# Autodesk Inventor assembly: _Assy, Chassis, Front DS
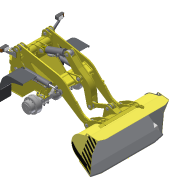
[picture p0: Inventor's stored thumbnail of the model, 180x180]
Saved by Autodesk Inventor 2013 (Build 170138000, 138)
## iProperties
Created: 2005-04
Part Number: _Assy, Chassis, Front DS
Document SubType Name: Assembly
Designer: salex
Manufacturer: Standard
Standards Organization: Custom
Author: salex
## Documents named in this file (35)
- C:\Product Design Suite 2013 Test Drive\Dynamic Simulation\Workspace\_Assy, Chassis, Front DS.iam
- C:\Product Design Suite 2013 Test Drive\Dynamic Simulation\Workspace\Assy, Chassis, Front\PK46.43.00.005.ipt
- C:\Product Design Suite 2013 Test Drive\Dynamic Simulation\Workspace\Assy, Chassis, Front\PK46.25.02.010.iam
- C:\Product Design Suite 2013 Test Drive\Dynamic Simulation\Workspace\Assy, Chassis, Front\PK46.16.10.000.iam
- C:\Product Design Suite 2013 Test Drive\Dynamic Simulation\Workspace\Assy, Chassis, Front\PK46.25.03.000.iam
- C:\Product Design Suite 2013 Test Drive\Dynamic Simulation\Workspace\Assy, Chassis, Front\PK46.43.01.010.iam
- C:\Product Design Suite 2013 Test Drive\Dynamic Simulation\Workspace\Assy, Chassis, Front\PK46.04.00.002.ipt
- C:\Product Design Suite 2013 Test Drive\Dynamic Simulation\Workspace\Assy, Chassis, Front\PK46.43.02.010.iam
- C:\Product Design Suite 2013 Test Drive\Dynamic Simulation\Workspace\Assy, Chassis, Front\PK46.04.00.030.iam
- C:\Product Design Suite 2013 Test Drive\Dynamic Simulation\Workspace\Assy, Chassis, Front\027.13.14.227.ipt
- C:\Product Design Suite 2013 Test Drive\Dynamic Simulation\Workspace\Assy, Chassis, Front\027.13.12.227.ipt
- C:\Product Design Suite 2013 Test Drive\Dynamic Simulation\Workspace\Assy, Chassis, Front\PK46.53.20.000.iam
- C:\Product Design Suite 2013 Test Drive\Dynamic Simulation\Workspace\Assy, Chassis, Front\PK46.25.00.010.iam
- C:\Product Design Suite 2013 Test Drive\Dynamic Simulation\Workspace\Assy, Chassis, Front\PK46.25.00.005.ipt
- C:\Product Design Suite 2013 Test Drive\Dynamic Simulation\Workspace\Assy, Chassis, Front\PK46.25.00.008.ipt
- C:\Product Design Suite 2013 Test Drive\Dynamic Simulation\Workspace\Assy, Chassis, Front\PK46.25.00.007.ipt
- C:\Product Design Suite 2013 Test Drive\Dynamic Simulation\Workspace\Assy, Chassis, Front\PK46.25.00.030.iam
- C:\Product Design Suite 2013 Test Drive\Dynamic Simulation\Workspace\Assy, Chassis, Front\PK46.25.00.020.iam
- C:\Product Design Suite 2013 Test Drive\Dynamic Simulation\Workspace\Assy, Chassis, Front\PK46.25.00.006.ipt
- C:\Product Design Suite 2013 Test Drive\Dynamic Simulation\Workspace\Assy, Chassis, Front\PK46.41.00.200-01.iam
- C:\Product Design Suite 2013 Test Drive\Dynamic Simulation\Workspace\Assy, Chassis, Front\PK46.20.10.000.iam
- C:\Product Design Suite 2013 Test Drive\Dynamic Simulation\Workspace\Assy, Chassis, Front\PK46.04.00.031.iam
- C:\Product Design Suite 2013 Test Drive\Dynamic Simulation\Workspace\Assy, Chassis, Front\027.13.15.227.ipt
- C:\Product Design Suite 2013 Test Drive\Dynamic Simulation\Workspace\Assy, Chassis, Front\027.13.16.227.ipt
- C:\Product Design Suite 2013 Test Drive\Dynamic Simulation\Workspace\Assy, Chassis, Front\PK46.43.04.020.iam
- C:\Product Design Suite 2013 Test Drive\Dynamic Simulation\Workspace\Assy, Chassis, Front\PK46.43.03.020.iam
- C:\Product Design Suite 2013 Test Drive\Dynamic Simulation\Workspace\Assy, Chassis, Front\PK46.41.00.200-02.iam
- C:\Product Design Suite 2013 Test Drive\Dynamic Simulation\Workspace\Assy, Chassis, Front\PK46.53.20.001.iam
- C:\Product Design Suite 2013 Test Drive\Dynamic Simulation\Workspace\Assy, Chassis, Front\PK46.21.01.100.iam
- C:\Product Design Suite 2013 Test Drive\Dynamic Simulation\Workspace\Assy, Chassis, Front\PK46.80.00.000.iam
- C:\Product Design Suite 2013 Test Drive\Dynamic Simulation\Workspace\Assy, Chassis, Front\PK46.21.01.200.iam
- C:\Product Design Suite 2013 Test Drive\Dynamic Simulation\Workspace\Assy, Chassis, Front\PK46.21.01.090.ipt
- C:\Product Design Suite 2013 Test Drive\Dynamic Simulation\Workspace\Assy, Chassis, Front\PK46.21.01.091.ipt
- C:\Product Design Suite 2013 Test Drive\Dynamic Simulation\Workspace\Assy, Chassis, Front\PK46.21.01.092.ipt
- C:\Product Design Suite 2013 Test Drive\Dynamic Simulation\Workspace\Assy, Chassis, Front\PK46.25.01.000.iam
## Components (125 placed, 34 different names)
1. PK46.21.01.100:1 [sub-assembly] — Вставка:1, Совмещение:1, Совмещение:3, Угол:1, Совмещение:4, Вставка:6, Вставка:9, Угол:2, Вставка:10, Вставка:20, Вставка:21, Вставка:22, Вставка:23, Угол:11, Угол:12, Угол:13, Угол:14, Mate:20, Угол:19, Mate:21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
2. PK46.80.00.000:1 [sub-assembly] — Mate Bucket yoke, tangent boom down, Заподлицо:7, Заподлицо:9, Вставка:35, Вставка:36, Вставка:45, Вставка:46, Вставка:48, Вставка:49, Mate:88, Mate:107, Mate:108
3. PK46.21.01.200:1 [sub-assembly] — Вставка:1, Совмещение:1, Вставка:12, Вставка:13, Вставка:14, Вставка:15, Угол:3, Угол:4, Угол:5, Угол:6, Совмещение:18, Insert:99, Insert:100, Insert:101, Insert:102
4. PK46.25.02.010:1 [sub-assembly] — Совмещение:6, Совмещение:7, Совмещение:11, Вставка:27, Совмещение:48, Вставка:28, Вставка:29, Вставка:40, Вставка:41, Совмещение:49, Mate:94, Mate:95, Mate:96, Mate:105, Mate:106, Mate:109
5. PK46.25.03.000:1 [sub-assembly] — Совмещение:6, Совмещение:7, Mate Bucket yoke, Mate:88, Mate:108, Mate:109
6. PK46.16.10.000:1 [sub-assembly] — Совмещение:3, Угол:1, Совмещение:4, Insert:111, Insert:112, Insert:113, Insert:114, Insert:116, Insert:121, Insert:122, Insert:123
7. PK46.43.03.020:1 [sub-assembly] — Совмещение:9, Вставка:6, Угол:21, Mate:100
8. PK46.43.01.010:1 [sub-assembly] — Совмещение:47, Вставка:76, Вставка:77, Вставка:79
9. PK46.43.01.010:2 [sub-assembly] — Совмещение:9, Угол:21, Вставка:81, Вставка:82, Mate:100
10. PK46.04.00.002:1 — Вставка:9, Угол:2
11. PK46.43.04.020:1 [sub-assembly] — Вставка:10, Совмещение:12, Angle:25, _Mate:101 extension cyl middle
12. PK46.43.02.010:1 [sub-assembly] — Совмещение:11, Совмещение:12, Angle:25, _Mate:101 extension cyl middle, Mate:105, Flush:23
13. PK46.53.20.000:1 [sub-assembly] — Mate:20, Угол:19, Mate:21, Flush:16
14. PK46.53.20.001:1 [sub-assembly]
15. PK46.21.01.090:1 — Совмещение:23, Заподлицо:4, Совмещение:24, Совмещение:25, Совмещение:27
16. PK46.21.01.090:2 — Совмещение:25, Совмещение:26, Совмещение:27
17. PK46.21.01.091:1 — Заподлицо:7, Заподлицо:9
18. PK46.43.00.005:1 — Вставка:25, Совмещение:41, Вставка:26
19. PK46.43.00.005:2 — Вставка:25, Совмещение:41, Совмещение:42, Flush:20, Flush:21
20. PK46.21.01.092:1 — Совмещение:44, Совмещение:45, Совмещение:46
21. PK46.43.03.020:2 [sub-assembly] — Совмещение:47, Совмещение:83, Mate:89, Flush:17
22. PK46.25.00.010:1 [sub-assembly] — Вставка:27, Совмещение:48
23. PK46.25.00.005:1 — Вставка:28
24. PK46.25.00.005:2 — Вставка:29, Вставка:30
25. PK46.25.00.008:1 — Вставка:30, Вставка:31, Flush:23
26. PK46.25.00.007:1 — Вставка:31
27. PK46.25.00.030:1 [sub-assembly] — Flush:12, Mate:96, Mate:97, Mate:98
28. PK46.25.00.008:2 — Вставка:34, Mate:98
29. PK46.25.00.005:4 — Вставка:36, Вставка:38
30. PK46.25.00.007:2 — Вставка:34, Mate:97
31. PK46.25.00.010:2 [sub-assembly] — Вставка:37
32. PK46.25.00.008:3 — Вставка:38, Вставка:39
33. PK46.25.00.007:3 — Вставка:39
34. PK46.25.00.005:7 — Вставка:41, Вставка:43
35. PK46.25.00.005:8 — Вставка:40, Вставка:42
36. PK46.25.00.010:3 [sub-assembly] — Вставка:42, Совмещение:49
37. PK46.25.00.007:4 — Вставка:44
38. PK46.25.00.008:4 — Вставка:43, Вставка:44
39. PK46.25.00.020:1 [sub-assembly] — Вставка:45, Mate:99
40. PK46.25.00.008:5 — Вставка:46, Вставка:47
41. PK46.25.00.007:5 — Вставка:47
42. PK46.25.00.007:6 — Вставка:50
43. PK46.25.00.020:2 [sub-assembly] — Вставка:48
44. PK46.25.00.005:5 — Вставка:35, Вставка:37
45. PK46.25.00.008:6 — Вставка:49, Вставка:50
46. PK46.25.00.020:3 [sub-assembly] — Вставка:60, Mate:102, Mate:104
47. PK46.25.00.020:4 [sub-assembly] — Вставка:53, Совмещение:83, Mate:89, Mate:102, Mate:103, Mate:104
48. PK46.25.00.006:1 — Вставка:53
49. PK46.25.00.006:2 — Вставка:52, Вставка:54
50. PK46.25.00.008:7 — Вставка:54, Вставка:55
51. PK46.25.00.007:7 — Вставка:55
52. PK46.25.00.006:3 — Insert:56, Вставка:60
53. PK46.25.00.006:4 — Вставка:57
54. PK46.25.00.008:8 — Вставка:58, Вставка:59
55. PK46.25.00.007:8 — Вставка:59
56. PK46.25.00.020:5 [sub-assembly] — Вставка:69
57. PK46.25.00.006:5 — Insert:61, Вставка:70
58. PK46.25.00.006:6 — Вставка:69
59. PK46.25.00.008:9 — Вставка:65, Вставка:68
60. PK46.25.00.007:9 — Вставка:68
61. PK46.25.00.020:6 [sub-assembly] — Вставка:70, Mate:90
62. PK46.25.00.006:7 — Вставка:63, Вставка:65
63. PK46.25.00.006:8 — Вставка:62, Вставка:66
64. PK46.25.00.008:10 — Вставка:66, Вставка:67
65. PK46.25.00.007:10 — Вставка:67
66. PK46.25.00.010:4 [sub-assembly] — Вставка:73
67. PK46.25.00.005:9 — Вставка:71
68. PK46.25.00.005:10 — Вставка:72
69. PK46.25.00.008:11 — Вставка:74, Вставка:75
70. PK46.25.00.007:11 — Вставка:75
71. PK46.25.00.005:11 — Вставка:77
72. PK46.25.00.005:12 — Вставка:76, Вставка:78
73. PK46.25.00.010:5 [sub-assembly] — Вставка:78, _ Mate:93 Left Fore Cyl, Mate:111
74. PK46.25.00.007:12 — Вставка:80
75. PK46.25.00.008:12 — Вставка:79, Вставка:80
76. PK46.25.00.005:13 — Вставка:82, Вставка:83
77. PK46.25.00.005:14 — Вставка:81, Вставка:84
78. PK46.25.00.010:6 [sub-assembly] — Вставка:83, _ Mate:92 Right Fore Cyl, Mate:110
79. PK46.25.00.007:14 — Вставка:85
80. PK46.25.00.008:14 — Вставка:84, Вставка:85
81. PK46.41.00.200-01:1 [sub-assembly] — Flush:15, Flush:16, Flush:18
82. PK46.41.00.200-02:1 [sub-assembly]
83. PK46.25.01.000:1 [sub-assembly] — Mate:90, Mate:91, _ Mate:92 Right Fore Cyl, _ Mate:93 Left Fore Cyl, Mate:94, Mate:95, Flush:12, Mate:99, Mate:106, Mate:107, Mate:110, Mate:111
84. PK46.20.10.000:1 [sub-assembly] — Insert:111
85. PK46.20.10.000:2 [sub-assembly] — Insert:112
86. PK46.20.10.000:3 [sub-assembly] — Insert:113
87. PK46.20.10.000:4 [sub-assembly] — Insert:114
88. PK46.04.00.031:1 [sub-assembly] — Insert:115
89. PK46.04.00.031:2 [sub-assembly] — Insert:118
90. PK46.04.00.031:3 [sub-assembly] — Insert:119
91. PK46.04.00.031:4 [sub-assembly] — Insert:120
92. 027.13.15.227:1 — Insert:116, Insert:117
93. 027.13.16.227:1 — Insert:117
94. 027.13.15.227:2 — Insert:121, Insert:124
95. 027.13.15.227:3 — Insert:122, Insert:125
96. 027.13.15.227:4 — Insert:123, Insert:126
97. 027.13.16.227:2 — Insert:124
98. 027.13.16.227:3 — Insert:125
99. 027.13.16.227:4 — Insert:126
100. PK46.43.00.005:3 — Insert:127, Insert:128, Flush:22
101. PK46.43.00.005:4 — Flush:20, Flush:21, Flush:22
102. PK46.04.00.030:1 [sub-assembly] — Вставка:13, Угол:4
103. PK46.04.00.030:2 [sub-assembly] — Вставка:15, Угол:6
104. PK46.04.00.030:3 [sub-assembly] — Вставка:12, Угол:3
105. PK46.04.00.030:4 [sub-assembly] — Вставка:14, Угол:5
106. PK46.04.00.030:5 [sub-assembly] — Insert:99
107. PK46.04.00.030:6 [sub-assembly] — Insert:100
108. PK46.04.00.030:7 [sub-assembly] — Insert:101
109. PK46.04.00.030:8 [sub-assembly] — Insert:102
110. 027.13.14.227:1 — Вставка:16, Угол:7, Вставка:20, Угол:11
111. 027.13.14.227:2 — Вставка:17, Угол:8, Вставка:21, Угол:13
112. 027.13.14.227:3 — Вставка:19, Угол:10, Вставка:22, Угол:12
113. 027.13.14.227:4 — Вставка:18, Угол:9, Вставка:23, Угол:14
114. 027.13.14.227:5 — Insert:103, Insert:107
115. 027.13.14.227:6 — Insert:104, Insert:108
116. 027.13.14.227:7 — Insert:105, Insert:109
117. 027.13.14.227:8 — Insert:106, Insert:110
118. 027.13.12.227:1 — Вставка:16, Угол:7
119. 027.13.12.227:2 — Вставка:17, Угол:8
120. 027.13.12.227:3 — Вставка:18, Угол:9
121. 027.13.12.227:4 — Вставка:19, Угол:10
122. 027.13.12.227:5 — Insert:107
123. 027.13.12.227:6 — Insert:108
124. 027.13.12.227:7 — Insert:109
125. 027.13.12.227:8 — Insert:110
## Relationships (184: Insert 103, Mate 50, Angle 17, Flush 13, Tangent 1)
- Вставка:1 [Insert]: PK46.21.01.100:1 ↔ PK46.21.01.200:1
- Совмещение:1 [Mate]: PK46.21.01.100:1 ↔ PK46.21.01.200:1
- Совмещение:3 [Mate]: PK46.21.01.100:1 ↔ PK46.16.10.000:1
- Угол:1 [Angle]: PK46.21.01.100:1 ↔ PK46.16.10.000:1
- Совмещение:4 [Mate]: PK46.21.01.100:1 ↔ PK46.16.10.000:1
- Совмещение:6 [Mate]: PK46.25.02.010:1 ↔ PK46.25.03.000:1
- Совмещение:7 [Mate]: PK46.25.02.010:1 ↔ PK46.25.03.000:1
- Mate Bucket yoke: PK46.80.00.000:1 ↔ PK46.25.03.000:1
- Совмещение:9 [Mate]: PK46.43.03.020:1 ↔ PK46.43.01.010:2
- Вставка:6 [Insert]: PK46.21.01.100:1 ↔ PK46.43.03.020:1
- Вставка:9 [Insert]: PK46.21.01.100:1 ↔ PK46.04.00.002:1
- Угол:2 [Angle]: PK46.21.01.100:1 ↔ PK46.04.00.002:1
- Вставка:10 [Insert]: PK46.21.01.100:1 ↔ PK46.43.04.020:1
- Совмещение:11 [Mate]: PK46.25.02.010:1 ↔ PK46.43.02.010:1
- Совмещение:12 [Mate]: PK46.43.04.020:1 ↔ PK46.43.02.010:1
- Вставка:12 [Insert]: PK46.21.01.200:1 ↔ PK46.04.00.030:3
- Вставка:13 [Insert]: PK46.21.01.200:1 ↔ PK46.04.00.030:1
- Вставка:14 [Insert]: PK46.21.01.200:1 ↔ PK46.04.00.030:4
- Вставка:15 [Insert]: PK46.21.01.200:1 ↔ PK46.04.00.030:2
- Угол:3 [Angle]: PK46.21.01.200:1 ↔ PK46.04.00.030:3
- Угол:4 [Angle]: PK46.21.01.200:1 ↔ PK46.04.00.030:1
- Угол:5 [Angle]: PK46.21.01.200:1 ↔ PK46.04.00.030:4
- Угол:6 [Angle]: PK46.21.01.200:1 ↔ PK46.04.00.030:2
- Вставка:16 [Insert]: 027.13.14.227:1 ↔ 027.13.12.227:1
- Вставка:17 [Insert]: 027.13.14.227:2 ↔ 027.13.12.227:2
- Вставка:18 [Insert]: 027.13.14.227:4 ↔ 027.13.12.227:3
- Вставка:19 [Insert]: 027.13.14.227:3 ↔ 027.13.12.227:4
- Угол:7 [Angle]: 027.13.14.227:1 ↔ 027.13.12.227:1
- Угол:8 [Angle]: 027.13.14.227:2 ↔ 027.13.12.227:2
- Угол:9 [Angle]: 027.13.14.227:4 ↔ 027.13.12.227:3
- Угол:10 [Angle]: 027.13.14.227:3 ↔ 027.13.12.227:4
- Вставка:20 [Insert]: PK46.21.01.100:1 ↔ 027.13.14.227:1
- Вставка:21 [Insert]: PK46.21.01.100:1 ↔ 027.13.14.227:2
- Вставка:22 [Insert]: PK46.21.01.100:1 ↔ 027.13.14.227:3
- Вставка:23 [Insert]: PK46.21.01.100:1 ↔ 027.13.14.227:4
- Угол:11 [Angle]: PK46.21.01.100:1 ↔ 027.13.14.227:1
- Угол:12 [Angle]: PK46.21.01.100:1 ↔ 027.13.14.227:3
- Угол:13 [Angle]: PK46.21.01.100:1 ↔ 027.13.14.227:2
- Угол:14 [Angle]: PK46.21.01.100:1 ↔ 027.13.14.227:4
- Совмещение:18 [Mate]: PK46.21.01.200:1
- Mate:20: PK46.21.01.100:1 ↔ PK46.53.20.000:1
- Угол:19 [Angle]: PK46.21.01.100:1 ↔ PK46.53.20.000:1
- Mate:21: PK46.21.01.100:1 ↔ PK46.53.20.000:1
- Совмещение:23 [Mate]: PK46.21.01.100:1 ↔ PK46.21.01.090:1
- Заподлицо:4 [Flush]: PK46.21.01.100:1 ↔ PK46.21.01.090:1
- Совмещение:24 [Mate]: PK46.21.01.100:1 ↔ PK46.21.01.090:1
- Совмещение:25 [Mate]: PK46.21.01.090:1 ↔ PK46.21.01.090:2
- Совмещение:26 [Mate]: PK46.21.01.100:1 ↔ PK46.21.01.090:2
- Совмещение:27 [Mate]: PK46.21.01.090:1 ↔ PK46.21.01.090:2
- Угол:21 [Angle]: PK46.43.03.020:1 ↔ PK46.43.01.010:2
- tangent boom down: PK46.80.00.000:1
- Заподлицо:7 [Flush]: PK46.80.00.000:1 ↔ PK46.21.01.091:1
- Заподлицо:9 [Flush]: PK46.80.00.000:1 ↔ PK46.21.01.091:1
- Вставка:25 [Insert]: PK46.43.00.005:1 ↔ PK46.43.00.005:2
- Совмещение:41 [Mate]: PK46.43.00.005:1 ↔ PK46.43.00.005:2
- Вставка:26 [Insert]: PK46.21.01.100:1 ↔ PK46.43.00.005:1
- Совмещение:42 [Mate]: PK46.21.01.100:1 ↔ PK46.43.00.005:2
- Совмещение:44 [Mate]: PK46.21.01.100:1 ↔ PK46.21.01.092:1
- Совмещение:45 [Mate]: PK46.21.01.100:1 ↔ PK46.21.01.092:1
- Совмещение:46 [Mate]: PK46.21.01.100:1 ↔ PK46.21.01.092:1
- Совмещение:47 [Mate]: PK46.43.01.010:1 ↔ PK46.43.03.020:2
- Вставка:27 [Insert]: PK46.25.02.010:1 ↔ PK46.25.00.010:1
- Совмещение:48 [Mate]: PK46.25.02.010:1 ↔ PK46.25.00.010:1
- Вставка:28 [Insert]: PK46.25.02.010:1 ↔ PK46.25.00.005:1
- Вставка:29 [Insert]: PK46.25.02.010:1 ↔ PK46.25.00.005:2
- Вставка:30 [Insert]: PK46.25.00.005:2 ↔ PK46.25.00.008:1
- Вставка:31 [Insert]: PK46.25.00.008:1 ↔ PK46.25.00.007:1
- Вставка:34 [Insert]: PK46.25.00.008:2 ↔ PK46.25.00.007:2
- Вставка:35 [Insert]: PK46.80.00.000:1 ↔ PK46.25.00.005:5
- Вставка:36 [Insert]: PK46.80.00.000:1 ↔ PK46.25.00.005:4
- Вставка:37 [Insert]: PK46.25.00.010:2 ↔ PK46.25.00.005:5
- Вставка:38 [Insert]: PK46.25.00.005:4 ↔ PK46.25.00.008:3
- Вставка:39 [Insert]: PK46.25.00.008:3 ↔ PK46.25.00.007:3
- Вставка:40 [Insert]: PK46.25.02.010:1 ↔ PK46.25.00.005:8
- Вставка:41 [Insert]: PK46.25.02.010:1 ↔ PK46.25.00.005:7
- Вставка:42 [Insert]: PK46.25.00.005:8 ↔ PK46.25.00.010:3
- Совмещение:49 [Mate]: PK46.25.02.010:1 ↔ PK46.25.00.010:3
- Вставка:43 [Insert]: PK46.25.00.005:7 ↔ PK46.25.00.008:4
- Вставка:44 [Insert]: PK46.25.00.007:4 ↔ PK46.25.00.008:4
- Вставка:45 [Insert]: PK46.80.00.000:1 ↔ PK46.25.00.020:1
- Вставка:46 [Insert]: PK46.80.00.000:1 ↔ PK46.25.00.008:5
- Вставка:47 [Insert]: PK46.25.00.008:5 ↔ PK46.25.00.007:5
- Вставка:48 [Insert]: PK46.80.00.000:1 ↔ PK46.25.00.020:2
- Вставка:49 [Insert]: PK46.80.00.000:1 ↔ PK46.25.00.008:6
- Вставка:50 [Insert]: PK46.25.00.007:6 ↔ PK46.25.00.008:6
- Вставка:52 [Insert]: PK46.21.01.100:1 ↔ PK46.25.00.006:2
- Вставка:53 [Insert]: PK46.25.00.020:4 ↔ PK46.25.00.006:1
- Вставка:54 [Insert]: PK46.25.00.006:2 ↔ PK46.25.00.008:7
- Вставка:55 [Insert]: PK46.25.00.008:7 ↔ PK46.25.00.007:7
- Вставка:57 [Insert]: PK46.21.01.100:1 ↔ PK46.25.00.006:4
- Insert:56: PK46.21.01.100:1 ↔ PK46.25.00.006:3
- Вставка:58 [Insert]: PK46.21.01.100:1 ↔ PK46.25.00.008:8
- Вставка:59 [Insert]: PK46.25.00.008:8 ↔ PK46.25.00.007:8
- Вставка:60 [Insert]: PK46.25.00.020:3 ↔ PK46.25.00.006:3
- Insert:61: PK46.21.01.100:1 ↔ PK46.25.00.006:5
- Вставка:62 [Insert]: PK46.21.01.100:1 ↔ PK46.25.00.006:8
- Вставка:63 [Insert]: PK46.21.01.100:1 ↔ PK46.25.00.006:7
- Вставка:65 [Insert]: PK46.25.00.008:9 ↔ PK46.25.00.006:7
- Вставка:66 [Insert]: PK46.25.00.006:8 ↔ PK46.25.00.008:10
- Вставка:67 [Insert]: PK46.25.00.008:10 ↔ PK46.25.00.007:10
- Вставка:68 [Insert]: PK46.25.00.008:9 ↔ PK46.25.00.007:9
- Вставка:69 [Insert]: PK46.25.00.020:5 ↔ PK46.25.00.006:6
- Вставка:70 [Insert]: PK46.25.00.006:5 ↔ PK46.25.00.020:6
- Вставка:71 [Insert]: PK46.21.01.100:1 ↔ PK46.25.00.005:9
- Вставка:72 [Insert]: PK46.21.01.100:1 ↔ PK46.25.00.005:10
- Вставка:73 [Insert]: PK46.21.01.100:1 ↔ PK46.25.00.010:4
- Вставка:74 [Insert]: PK46.21.01.100:1 ↔ PK46.25.00.008:11
- Вставка:75 [Insert]: PK46.25.00.008:11 ↔ PK46.25.00.007:11
- Вставка:76 [Insert]: PK46.43.01.010:1 ↔ PK46.25.00.005:12
- Вставка:77 [Insert]: PK46.43.01.010:1 ↔ PK46.25.00.005:11
- Вставка:78 [Insert]: PK46.25.00.005:12 ↔ PK46.25.00.010:5
- Вставка:79 [Insert]: PK46.43.01.010:1 ↔ PK46.25.00.008:12
- Вставка:80 [Insert]: PK46.25.00.007:12 ↔ PK46.25.00.008:12
- Вставка:81 [Insert]: PK46.43.01.010:2 ↔ PK46.25.00.005:14
- Вставка:82 [Insert]: PK46.43.01.010:2 ↔ PK46.25.00.005:13
- Вставка:83 [Insert]: PK46.25.00.005:13 ↔ PK46.25.00.010:6
- Вставка:84 [Insert]: PK46.25.00.005:14 ↔ PK46.25.00.008:14
- Вставка:85 [Insert]: PK46.25.00.007:14 ↔ PK46.25.00.008:14
- Совмещение:83 [Mate]: PK46.43.03.020:2 ↔ PK46.25.00.020:4
- Mate:88: PK46.80.00.000:1 ↔ PK46.25.03.000:1
- Mate:89: PK46.43.03.020:2 ↔ PK46.25.00.020:4
- Mate:90: PK46.25.00.020:6 ↔ PK46.25.01.000:1
- Mate:91: PK46.21.01.100:1 ↔ PK46.25.01.000:1
- _ Mate:92 Right Fore Cyl [Mate]: PK46.25.00.010:6 ↔ PK46.25.01.000:1
- _ Mate:93 Left Fore Cyl [Mate]: PK46.25.00.010:5 ↔ PK46.25.01.000:1
- Mate:94: PK46.25.02.010:1 ↔ PK46.25.01.000:1
- Mate:95: PK46.25.02.010:1 ↔ PK46.25.01.000:1
- Flush:12: PK46.25.00.030:1 ↔ PK46.25.01.000:1
- Mate:96: PK46.25.02.010:1 ↔ PK46.25.00.030:1
- Mate:97: PK46.25.00.030:1 ↔ PK46.25.00.007:2
- Mate:98: PK46.25.00.030:1 ↔ PK46.25.00.008:2
- Mate:99: PK46.25.00.020:1 ↔ PK46.25.01.000:1
- Flush:15: PK46.21.01.100:1 ↔ PK46.41.00.200-01:1
- Flush:16: PK46.53.20.000:1 ↔ PK46.41.00.200-01:1
- Flush:17: PK46.21.01.100:1 ↔ PK46.43.03.020:2
- Flush:18: PK46.21.01.100:1 ↔ PK46.41.00.200-01:1
- Angle:25: PK46.43.04.020:1 ↔ PK46.43.02.010:1
- Insert:99: PK46.21.01.200:1 ↔ PK46.04.00.030:5
- Insert:100: PK46.21.01.200:1 ↔ PK46.04.00.030:6
- Insert:101: PK46.21.01.200:1 ↔ PK46.04.00.030:7
- Insert:102: PK46.21.01.200:1 ↔ PK46.04.00.030:8
- Insert:103: PK46.21.01.100:1 ↔ 027.13.14.227:5
- Insert:104: PK46.21.01.100:1 ↔ 027.13.14.227:6
- Insert:105: PK46.21.01.100:1 ↔ 027.13.14.227:7
- Insert:106: PK46.21.01.100:1 ↔ 027.13.14.227:8
- Insert:107: 027.13.14.227:5 ↔ 027.13.12.227:5
- Insert:108: 027.13.14.227:6 ↔ 027.13.12.227:6
- Insert:109: 027.13.14.227:7 ↔ 027.13.12.227:7
- Insert:110: 027.13.14.227:8 ↔ 027.13.12.227:8
- Insert:111: PK46.16.10.000:1 ↔ PK46.20.10.000:1
- Insert:112: PK46.16.10.000:1 ↔ PK46.20.10.000:2
- Insert:113: PK46.16.10.000:1 ↔ PK46.20.10.000:3
- Insert:114: PK46.16.10.000:1 ↔ PK46.20.10.000:4
- Insert:115: PK46.21.01.100:1 ↔ PK46.04.00.031:1
- Insert:116: PK46.16.10.000:1 ↔ 027.13.15.227:1
- Insert:117: 027.13.15.227:1 ↔ 027.13.16.227:1
- Insert:118: PK46.21.01.100:1 ↔ PK46.04.00.031:2
- Insert:119: PK46.21.01.100:1 ↔ PK46.04.00.031:3
- Insert:120: PK46.21.01.100:1 ↔ PK46.04.00.031:4
- Insert:121: PK46.16.10.000:1 ↔ 027.13.15.227:2
- Insert:122: PK46.16.10.000:1 ↔ 027.13.15.227:3
- Insert:123: PK46.16.10.000:1 ↔ 027.13.15.227:4
- Insert:124: 027.13.15.227:2 ↔ 027.13.16.227:2
- Insert:125: 027.13.15.227:3 ↔ 027.13.16.227:3
- Insert:126: 027.13.15.227:4 ↔ 027.13.16.227:4
- Flush:19: PK46.21.01.100:1
- Mate:100: PK46.43.03.020:1 ↔ PK46.43.01.010:2
- _Mate:101 extension cyl middle [Mate]: PK46.43.04.020:1 ↔ PK46.43.02.010:1
- Mate:102: PK46.25.00.020:3 ↔ PK46.25.00.020:4
- Mate:103: PK46.21.01.100:1 ↔ PK46.25.00.020:4
- Mate:104: PK46.25.00.020:3 ↔ PK46.25.00.020:4
- Insert:127: PK46.21.01.100:1 ↔ PK46.43.00.005:3
- Insert:128: PK46.21.01.100:1 ↔ PK46.43.00.005:3
- Flush:20: PK46.43.00.005:2 ↔ PK46.43.00.005:4
- Flush:21: PK46.43.00.005:2 ↔ PK46.43.00.005:4
- Flush:22: PK46.43.00.005:3 ↔ PK46.43.00.005:4
- Mate:105: PK46.25.02.010:1 ↔ PK46.43.02.010:1
- Flush:23: PK46.43.02.010:1 ↔ PK46.25.00.008:1
- Mate:106: PK46.25.02.010:1 ↔ PK46.25.01.000:1
- Mate:107: PK46.80.00.000:1 ↔ PK46.25.01.000:1
- Mate:108: PK46.80.00.000:1 ↔ PK46.25.03.000:1
- Mate:109: PK46.25.02.010:1 ↔ PK46.25.03.000:1
- Mate:110: PK46.25.00.010:6 ↔ PK46.25.01.000:1
- Mate:111: PK46.25.00.010:5 ↔ PK46.25.01.000:1
